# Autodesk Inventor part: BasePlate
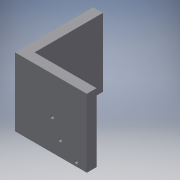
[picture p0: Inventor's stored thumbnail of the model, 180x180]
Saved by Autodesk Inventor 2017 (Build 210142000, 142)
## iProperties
Created: 2017-04
Part Number: BasePlate
Material: Generic
Document SubType Name: Modeling
Designer: 1460374
Density: 1 g/cm^3
Appearance: Default
Author: 1460374
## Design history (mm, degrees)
sketch "Sketch1"
  geometry: L1 (70, 70)-(-70, 70); L2 (-70, 70)-(-70, -70); L3 (-70, -70)-(70, -70); L4 (70, -70)-(70, 70); L5 (70, 70)-(-70, -70); L6 (-70, 70)-(70, -70); 2 further points
  constraints: 12 end point, 2 midpoint, 2 parallel, 1 coincident, 1 horizontal, 1 perpendicular
  dimensions: "d0" = 140 distance of L3.end L2.end; "d1" = 140 distance of L2.end L1.end
extrude "Extrusion1" new body sketch "Sketch1" distance "d2" = 20; taper "d3" = 0 deg
sketch "Sketch2"
  geometry: L1 (-70, 70)-(-70, -70) reference; L2 (-70, -70)-(-90, -70); L3 (-90, -70)-(-90, 70); L4 (-90, 70)-(-70, 70); L5 (-70, 70)-(-70, -70); 1 further point
  constraints: 8 end point, 2 parallel, 1 horizontal, 1 perpendicular
  dimensions: "d4" = 20 distance of L3.end L4.end
extrude "Extrusion2" join sketch "Sketch2" distance "d5" = 20; taper "d6" = 0 deg
sketch "Sketch3"
  geometry: L1 (70, -70)-(-90, -70) reference; L2 (70, 70)-(-90, 70) reference; L3 (-90, -70)-(-70, -70); L4 (-70, -70)-(-70, 70); L5 (-70, 70)-(-90, 70); L6 (-90, 70)-(-90, -70); 1 further point
  constraints: 8 end point, 2 parallel, 1 horizontal, 1 perpendicular, 1 point on line
  dimensions: "d7" = 20 distance of L5.end L4.end
extrude "Extrusion3" join sketch "Sketch3" distance "d8" = 127; taper "d9" = 0 deg
sketch "Sketch5"
  geometry: C1 r 3.225 at (-111.549, 9.601) reference; C2 r 3.225 at (-78.799, 25.976) reference; C3 r 3.225 at (-56.581, 58.847) reference; 1 further point
extrude "Extrusion5" cut sketch "Sketch5" stored distance "d12" = 25.4; taper "d13" = 0 deg
body "Solid1"
node "Reference10"
node "Reference11"
node "Reference12"
